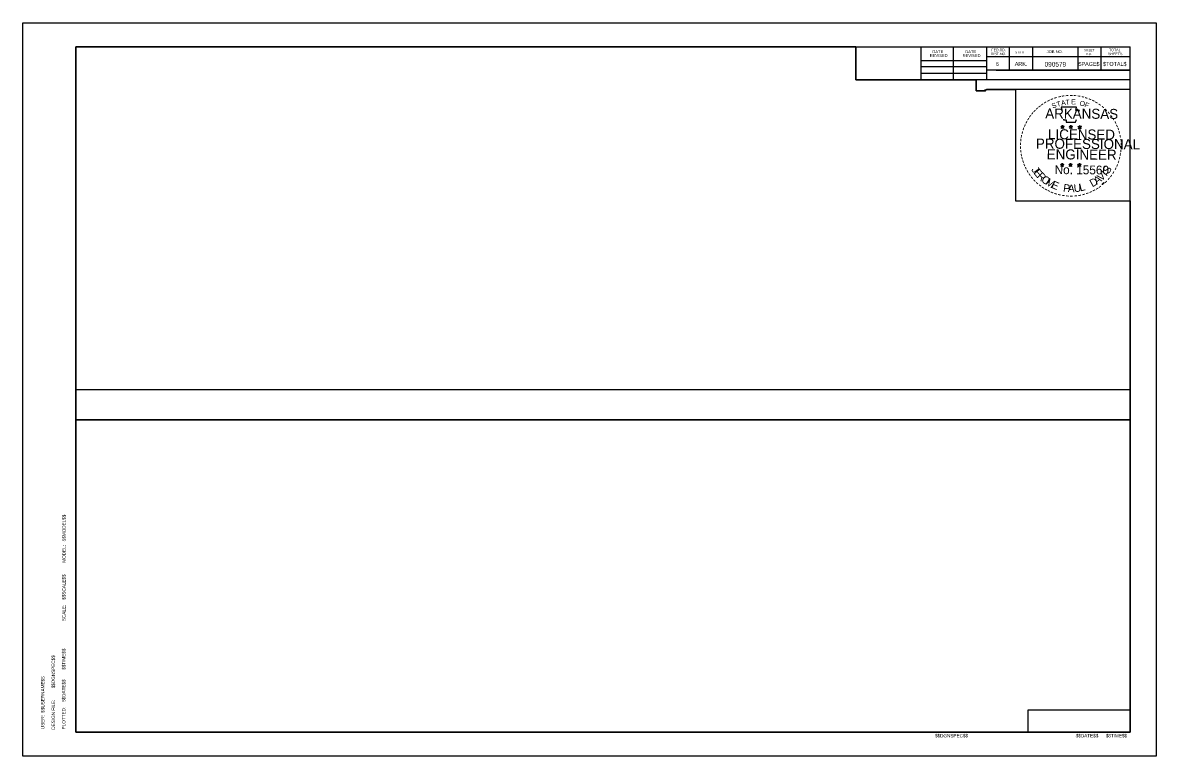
# Model space of a CAD drawing. Extents: x -1.6 to 32.4, y -0.7 to 21.3.
import ezdxf

# ---------------------------------------------------------------- set-up
doc = ezdxf.new("R2010")
doc.units = 0
for name, color, linetype in [('Level 3', 7, 'Continuous'), ('Level 48', 7, 'Continuous'), ('Level 49', 7, 'Continuous'), ('Level 63', 7, 'Continuous'), ('R_Border', 7, 'Continuous'), ('R_Border Notes', 7, 'Continuous'), ('R_Border Prelim', 7, 'Continuous'), ('R_No Plot', 7, 'Continuous')]:
    doc.layers.add(name, color=color, linetype=linetype)

msp = doc.modelspace()

# ---------------------------------------------------------------- linework, layer by layer
at = {"layer": 'Level 3'}
msp.add_lwpolyline([(-0.001, -0.001), (31.617, -0.001), (31.617, 19.265), (27.307, 19.265), (27.211, 19.232), (26.999, 19.232), (26.999, 19.557), (23.391, 19.557), (23.391, 20.545), (23.391, 20.545), (23.391, 20.545), (-0.001, 20.545)], close=True, dxfattribs=at)
at = {"layer": 'Level 48'}
for p, q in [((-0.001, 20.545), (-0.001, -0.001)), ((23.391, 19.557), (23.391, 20.545)), ((26.999, 19.557), (23.391, 19.557)), ((26.999, 19.232), (26.999, 19.557)), ((27.211, 19.232), (26.999, 19.232)), ((27.307, 19.265), (27.211, 19.232)), ((31.617, 19.265), (27.307, 19.265)), ((31.617, -0.001), (31.617, 19.265)), ((-0.001, -0.001), (31.617, -0.001))]:
    msp.add_line(p, q, dxfattribs=at)
msp.add_lwpolyline([(23.391, 20.545), (23.391, 20.545), (23.391, 20.545), (-0.001, 20.545)], dxfattribs=at)
at = {"layer": 'Level 63'}
for p, q in [((-0.002, 0.481), (-0.001, 10.271)), ((-0.001, 10.271), (31.617, 10.271)), ((31.617, 10.271), (31.617, -0.001)), ((-0.001, -0.001), (-0.002, 0.481)), ((-0.002, 0.481), (-0.002, 0.481)), ((31.617, -0.001), (-0.001, -0.001))]:
    msp.add_line(p, q, dxfattribs=at)
for points in [[(-0.001, 20.545), (23.391, 20.545), (23.391, 19.557), (27, 19.557), (27, 19.233), (27.274, 19.233), (27.307, 19.265), (28.175, 19.265), (28.175, 15.933), (31.617, 15.933), (31.617, 9.363), (-0.001, 9.363)], [(-0.001, 9.363), (31.617, 9.363), (31.617, 0.657), (28.548, 0.657), (28.546, 0), (-0.001, -0.001)]]:
    msp.add_lwpolyline(points, close=True, dxfattribs=at)
at = {"layer": 'R_Border'}
msp.add_lwpolyline([(-1.598, 21.273), (32.402, 21.273), (32.402, -0.727), (-1.598, -0.727)], close=True, dxfattribs=at)
at = {"layer": 'R_Border Prelim'}
for p, q in [((29.534, 18.159), (29.588, 18.142)), ((29.534, 18.159), (29.573, 18.157)), ((29.534, 18.159), (29.573, 18.155)), ((29.534, 18.159), (29.569, 18.149)), ((29.534, 18.159), (29.569, 18.144)), ((29.534, 18.159), (29.569, 18.142)), ((29.534, 18.159), (29.569, 18.136)), ((29.556, 18.097), (29.588, 18.142)), ((29.556, 18.097), (29.569, 18.14)), ((29.556, 18.097), (29.573, 18.135)), ((29.556, 18.097), (29.575, 18.133)), ((29.556, 18.097), (29.581, 18.129)), ((29.556, 18.097), (29.588, 18.129)), ((29.556, 18.097), (29.588, 18.125)), ((29.588, 18.199), (29.581, 18.159)), ((29.588, 18.199), (29.581, 18.162)), ((29.588, 18.199), (29.584, 18.162)), ((29.588, 18.142), (29.588, 18.199)), ((29.588, 18.199), (29.597, 18.159)), ((29.588, 18.199), (29.595, 18.162)), ((29.588, 18.199), (29.59, 18.162)), ((29.64, 18.159), (29.588, 18.142)), ((29.619, 18.096), (29.588, 18.142)), ((29.619, 18.096), (29.588, 18.129)), ((29.619, 18.096), (29.588, 18.125)), ((29.64, 18.159), (29.592, 18.155)), ((29.619, 18.096), (29.592, 18.129)), ((29.64, 18.159), (29.597, 18.151)), ((29.64, 18.159), (29.597, 18.148)), ((29.619, 18.096), (29.597, 18.14)), ((29.619, 18.096), (29.597, 18.135)), ((29.619, 18.096), (29.603, 18.142)), ((29.64, 18.159), (29.605, 18.148)), ((29.64, 18.159), (29.61, 18.144)), ((29.64, 18.159), (29.612, 18.142)), ((29.784, 18.157), (29.838, 18.142)), ((29.784, 18.157), (29.823, 18.155)), ((29.784, 18.157), (29.823, 18.151)), ((29.784, 18.157), (29.823, 18.149)), ((29.784, 18.157), (29.821, 18.142)), ((29.784, 18.157), (29.821, 18.14)), ((29.784, 18.157), (29.821, 18.135)), ((29.807, 18.096), (29.838, 18.142)), ((29.807, 18.096), (29.823, 18.136)), ((29.807, 18.096), (29.823, 18.135)), ((29.807, 18.096), (29.825, 18.133)), ((29.807, 18.096), (29.831, 18.127)), ((29.807, 18.096), (29.838, 18.127)), ((29.807, 18.096), (29.838, 18.125)), ((29.838, 18.196), (29.831, 18.157)), ((29.838, 18.196), (29.831, 18.159)), ((29.838, 18.196), (29.832, 18.159)), ((29.838, 18.142), (29.838, 18.196)), ((29.838, 18.196), (29.847, 18.157)), ((29.838, 18.196), (29.845, 18.159)), ((29.838, 18.196), (29.84, 18.159)), ((29.89, 18.157), (29.838, 18.142)), ((29.869, 18.096), (29.838, 18.142)), ((29.869, 18.096), (29.838, 18.127)), ((29.869, 18.096), (29.838, 18.125)), ((29.89, 18.157), (29.844, 18.155)), ((29.869, 18.096), (29.844, 18.127)), ((29.89, 18.157), (29.847, 18.149)), ((29.89, 18.157), (29.847, 18.148)), ((29.869, 18.096), (29.847, 18.14)), ((29.869, 18.096), (29.847, 18.133)), ((29.869, 18.096), (29.853, 18.14)), ((29.89, 18.157), (29.855, 18.144)), ((29.89, 18.157), (29.86, 18.142)), ((29.89, 18.157), (29.862, 18.14)), ((30.049, 18.155), (30.103, 18.136)), ((30.049, 18.155), (30.092, 18.149)), ((30.049, 18.155), (30.088, 18.148)), ((30.049, 18.155), (30.088, 18.144)), ((30.049, 18.155), (30.086, 18.14)), ((30.049, 18.155), (30.086, 18.135)), ((30.049, 18.155), (30.086, 18.135)), ((30.07, 18.094), (30.103, 18.136)), ((30.07, 18.094), (30.088, 18.135)), ((30.07, 18.094), (30.092, 18.129)), ((30.07, 18.094), (30.092, 18.127)), ((30.07, 18.094), (30.103, 18.127)), ((30.07, 18.094), (30.099, 18.125)), ((30.07, 18.094), (30.107, 18.12)), ((30.103, 18.192), (30.094, 18.157)), ((30.103, 18.192), (30.099, 18.155)), ((30.103, 18.192), (30.099, 18.155)), ((30.103, 18.136), (30.103, 18.192)), ((30.103, 18.192), (30.114, 18.155)), ((30.103, 18.192), (30.11, 18.155)), ((30.103, 18.192), (30.107, 18.155)), ((30.155, 18.155), (30.103, 18.136)), ((30.133, 18.094), (30.103, 18.136)), ((30.133, 18.094), (30.103, 18.127)), ((30.133, 18.094), (30.103, 18.12)), ((30.155, 18.155), (30.108, 18.149)), ((30.133, 18.094), (30.108, 18.125)), ((30.155, 18.155), (30.114, 18.148)), ((30.155, 18.155), (30.114, 18.142)), ((30.133, 18.094), (30.114, 18.135)), ((30.133, 18.094), (30.114, 18.129)), ((30.133, 18.094), (30.118, 18.135)), ((30.155, 18.155), (30.121, 18.14)), ((30.155, 18.155), (30.123, 18.14)), ((30.155, 18.155), (30.129, 18.136)), ((29.527, 17.021), (29.581, 17.005)), ((29.527, 17.021), (29.566, 17.019)), ((29.527, 17.021), (29.564, 17.014)), ((29.527, 17.021), (29.564, 17.014)), ((29.527, 17.021), (29.564, 17.006)), ((29.527, 17.021), (29.564, 17.005)), ((29.527, 17.021), (29.564, 17.003)), ((29.545, 16.964), (29.581, 17.005)), ((29.545, 16.964), (29.564, 17.005)), ((29.581, 17.062), (29.569, 17.025)), ((29.581, 17.062), (29.573, 17.021)), ((29.581, 17.062), (29.575, 17.021)), ((29.581, 17.005), (29.581, 17.062)), ((29.581, 17.062), (29.588, 17.021)), ((29.581, 17.062), (29.588, 17.021)), ((29.581, 17.062), (29.581, 17.021)), ((29.632, 17.021), (29.581, 17.005)), ((29.61, 16.96), (29.581, 17.005)), ((29.632, 17.021), (29.584, 17.019)), ((29.632, 17.021), (29.588, 17.014)), ((29.632, 17.021), (29.588, 17.012)), ((29.61, 16.96), (29.588, 17.005)), ((29.632, 17.021), (29.595, 17.01)), ((29.61, 16.96), (29.595, 17.005)), ((29.632, 17.021), (29.599, 17.006)), ((29.632, 17.021), (29.603, 17.005)), ((29.777, 17.021), (29.831, 17.005)), ((29.777, 17.021), (29.816, 17.018)), ((29.777, 17.021), (29.816, 17.014)), ((29.777, 17.021), (29.816, 17.012)), ((29.777, 17.021), (29.814, 17.006)), ((29.777, 17.021), (29.814, 17.003)), ((29.777, 17.021), (29.814, 16.999)), ((29.795, 16.96), (29.831, 17.005)), ((29.795, 16.96), (29.816, 17.003)), ((29.831, 17.058), (29.821, 17.021)), ((29.831, 17.058), (29.823, 17.021)), ((29.831, 17.058), (29.825, 17.021)), ((29.831, 17.005), (29.831, 17.058)), ((29.831, 17.058), (29.838, 17.019)), ((29.831, 17.058), (29.838, 17.019)), ((29.831, 17.058), (29.831, 17.021)), ((29.881, 17.019), (29.831, 17.005)), ((29.86, 16.96), (29.831, 17.005)), ((29.881, 17.019), (29.836, 17.019)), ((29.881, 17.019), (29.838, 17.012)), ((29.881, 17.019), (29.838, 17.012)), ((29.86, 16.96), (29.838, 17.003)), ((29.881, 17.019), (29.845, 17.006)), ((29.86, 16.96), (29.845, 17.003)), ((29.881, 17.019), (29.851, 17.005)), ((29.881, 17.019), (29.853, 17.003)), ((30.042, 17.018), (30.095, 16.999)), ((30.042, 17.018), (30.081, 17.014)), ((30.042, 17.018), (30.081, 17.01)), ((30.042, 17.018), (30.079, 17.006)), ((30.042, 17.018), (30.079, 17.003)), ((30.042, 17.018), (30.077, 16.999)), ((30.042, 17.018), (30.077, 16.995)), ((30.095, 17.056), (30.086, 17.018)), ((30.095, 17.056), (30.088, 17.018)), ((30.095, 17.056), (30.092, 17.018)), ((30.095, 16.999), (30.095, 17.056)), ((30.095, 17.056), (30.103, 17.018)), ((30.095, 17.056), (30.103, 17.018)), ((30.095, 17.056), (30.095, 17.018)), ((30.147, 17.018), (30.095, 16.999)), ((30.147, 17.018), (30.101, 17.014)), ((30.147, 17.018), (30.103, 17.01)), ((30.147, 17.018), (30.103, 17.006)), ((30.147, 17.018), (30.114, 17.005)), ((30.147, 17.018), (30.116, 16.999)), ((30.147, 17.018), (30.118, 16.999)), ((29.545, 16.964), (29.566, 16.997)), ((29.545, 16.964), (29.568, 16.997)), ((29.545, 16.964), (29.581, 16.995)), ((29.545, 16.964), (29.573, 16.992)), ((29.545, 16.964), (29.581, 16.99)), ((29.61, 16.96), (29.577, 16.99)), ((29.61, 16.96), (29.581, 16.992)), ((29.61, 16.96), (29.582, 16.992)), ((29.61, 16.96), (29.588, 16.997)), ((29.795, 16.96), (29.816, 16.995)), ((29.795, 16.96), (29.818, 16.995)), ((29.795, 16.96), (29.823, 16.992)), ((29.795, 16.96), (29.831, 16.992)), ((29.795, 16.96), (29.831, 16.988)), ((29.86, 16.96), (29.829, 16.988)), ((29.86, 16.96), (29.831, 16.992)), ((29.86, 16.96), (29.832, 16.992)), ((29.86, 16.96), (29.838, 16.997)), ((30.062, 16.956), (30.095, 16.999)), ((30.062, 16.956), (30.079, 16.999)), ((30.062, 16.956), (30.081, 16.992)), ((30.062, 16.956), (30.084, 16.992)), ((30.062, 16.956), (30.088, 16.988)), ((30.062, 16.956), (30.094, 16.988)), ((30.062, 16.956), (30.095, 16.984)), ((30.125, 16.956), (30.094, 16.988)), ((30.125, 16.956), (30.094, 16.984)), ((30.125, 16.956), (30.095, 16.999)), ((30.125, 16.956), (30.099, 16.988)), ((30.125, 16.956), (30.103, 16.992)), ((30.125, 16.956), (30.107, 16.999)), ((30.125, 16.956), (30.108, 16.999))]:
    msp.add_line(p, q, dxfattribs=at)
for points in [[(29.545, 18.742), (29.582, 18.616)], [(30.071, 18.6), (30.094, 18.644), (29.988, 18.638), (30.012, 18.738), (29.545, 18.742)], [(29.618, 18.377), (29.618, 18.362), (29.701, 18.361), (29.694, 18.292), (29.973, 18.29), (30.003, 18.368)], [(29.588, 18.199), (29.619, 18.096), (29.534, 18.159), (29.64, 18.159), (29.556, 18.097), (29.588, 18.199)], [(29.838, 18.196), (29.869, 18.096), (29.784, 18.157), (29.89, 18.157), (29.807, 18.096), (29.838, 18.196)], [(30.103, 18.192), (30.133, 18.094), (30.049, 18.155), (30.155, 18.155), (30.07, 18.094), (30.103, 18.192)], [(29.581, 17.062), (29.61, 16.96), (29.527, 17.021), (29.632, 17.021), (29.545, 16.964), (29.581, 17.062)], [(29.831, 17.058), (29.86, 16.96), (29.777, 17.021), (29.881, 17.019), (29.795, 16.96), (29.831, 17.058)], [(30.095, 17.056), (30.125, 16.956), (30.042, 17.018), (30.147, 17.018), (30.062, 16.956), (30.095, 17.056)], [(30.79, 16.415), (30.783, 16.44), (30.827, 16.477)], [(30.824, 16.482), (30.831, 16.46), (30.786, 16.421)], [(30.831, 16.464), (30.786, 16.425)], [(30.831, 16.46), (30.788, 16.423)]]:
    msp.add_lwpolyline(points, dxfattribs=at)
for centre, radius in [((29.589, 18.141), 0.0259), ((29.589, 18.141), 0.0234), ((29.589, 18.141), 0.0217), ((29.589, 18.141), 0.0199), ((29.589, 18.141), 0.0174), ((29.589, 18.141), 0.0161), ((29.589, 18.141), 0.0149), ((29.589, 18.141), 0.0128), ((29.589, 18.141), 0.0112), ((29.589, 18.141), 0.00933), ((29.589, 18.141), 0.00744), ((29.589, 18.141), 0.00555), ((29.589, 18.141), 0.00445), ((29.589, 18.141), 0.00216), ((29.839, 18.139), 0.0259), ((29.839, 18.139), 0.0234), ((29.839, 18.139), 0.0217), ((29.839, 18.139), 0.0199), ((29.839, 18.139), 0.0174), ((29.839, 18.139), 0.0161), ((29.839, 18.139), 0.0149), ((29.839, 18.139), 0.0128), ((29.839, 18.139), 0.0112), ((29.839, 18.139), 0.00933), ((29.839, 18.139), 0.00744), ((29.839, 18.139), 0.00555), ((29.839, 18.139), 0.00445), ((29.839, 18.139), 0.00216), ((30.105, 18.136), 0.0259), ((30.105, 18.136), 0.0234), ((30.105, 18.136), 0.0217), ((30.105, 18.136), 0.0199), ((30.105, 18.136), 0.0174), ((30.105, 18.136), 0.0161), ((30.105, 18.136), 0.0149), ((30.105, 18.136), 0.0128), ((30.105, 18.136), 0.0112), ((30.105, 18.136), 0.00933), ((30.105, 18.136), 0.00744), ((30.105, 18.136), 0.00555), ((30.105, 18.136), 0.00445), ((30.105, 18.136), 0.00216), ((29.58, 17.004), 0.0259), ((29.58, 17.004), 0.0234), ((29.58, 17.004), 0.0217), ((29.58, 17.004), 0.0199), ((29.58, 17.004), 0.0174), ((29.58, 17.004), 0.0161), ((29.58, 17.004), 0.0149), ((29.58, 17.004), 0.0128), ((29.58, 17.004), 0.0112), ((29.58, 17.004), 0.00933), ((29.58, 17.004), 0.00744), ((29.58, 17.004), 0.00555), ((29.58, 17.004), 0.00445), ((29.58, 17.004), 0.00216), ((29.831, 17.003), 0.0259), ((29.831, 17.003), 0.0234), ((29.831, 17.003), 0.0217), ((29.831, 17.003), 0.0199), ((29.831, 17.003), 0.0174), ((29.831, 17.003), 0.0161), ((29.831, 17.003), 0.0149), ((29.831, 17.003), 0.0128), ((29.831, 17.003), 0.0112), ((29.831, 17.003), 0.00933), ((29.831, 17.003), 0.00744), ((29.831, 17.003), 0.00555), ((29.831, 17.003), 0.00445), ((29.831, 17.003), 0.00216), ((30.096, 16.999), 0.0259), ((30.096, 16.999), 0.0234), ((30.096, 16.999), 0.0217), ((30.096, 16.999), 0.0199), ((30.096, 16.999), 0.0174), ((30.096, 16.999), 0.0161), ((30.096, 16.999), 0.0149), ((30.096, 16.999), 0.0128), ((30.096, 16.999), 0.0112), ((30.096, 16.999), 0.00933), ((30.096, 16.999), 0.00744), ((30.096, 16.999), 0.00555), ((30.096, 16.999), 0.00445), ((30.096, 16.999), 0.00216)]:
    msp.add_circle(centre, radius, dxfattribs=at)
at = {"layer": 'R_No Plot'}
for p, q in [((-0.001, 20.545), (31.617, 20.545)), ((-0.001, -0.001), (-0.001, 20.545)), ((25.353, 19.557), (25.353, 20.545)), ((26.321, 19.557), (26.321, 20.545)), ((27.307, 20.545), (27.307, 19.557)), ((27.991, 20.545), (27.991, 19.851)), ((28.685, 20.545), (28.685, 19.851)), ((30.043, 20.545), (30.043, 19.851)), ((30.737, 20.545), (30.737, 19.851)), ((31.617, -0.001), (31.617, 20.545)), ((25.353, 20.143), (27.307, 20.143)), ((31.617, 20.251), (27.307, 20.251)), ((31.617, 20.253), (31.617, 20.253)), ((25.353, 19.957), (27.307, 19.957)), ((25.353, 19.763), (27.307, 19.763)), ((31.617, 19.851), (27.307, 19.851)), ((27.603, 19.851), (31.617, 19.851)), ((31.617, 19.557), (25.353, 19.557)), ((31.617, -0.001), (-0.001, -0.001))]:
    msp.add_line(p, q, dxfattribs=at)

# ---------------------------------------------------------------- texts
at = {"layer": 'Level 49'}
msp.add_text('JOB NO.', height=0.0879, dxfattribs=at).set_placement((29.112, 20.36))
at = {"layer": 'R_Border Notes'}
for s, p in [('$$DGNSPEC$$', (25.764, -0.159)), ('$$DATE$$', (29.986, -0.159)), ('$$TIME$$', (30.887, -0.159))]:
    msp.add_text(s, height=0.1, dxfattribs=at).set_placement(p)
at = {"layer": 'R_Border Prelim'}
for s, height, rotation, p in [('-', 0.24, 18.7785, (29.356, 18.914)), ('-', 0.24, 13.2326, (29.469, 18.95)), ('-', 0.24, 9.8217, (29.569, 18.974)), ('-', 0.24, 5.4992, (29.681, 18.989)), ('-', 0.24, 359.7886, (29.795, 19)), ('-', 0.24, 357.3454, (29.907, 18.996)), ('-', 0.24, 351.7641, (30.016, 18.987)), ('-', 0.24, 346.8073, (30.125, 18.97)), ('-', 0.24, 341.9386, (30.22, 18.944)), ('-', 0.24, 42.5646, (28.851, 18.596)), ('-', 0.24, 38.5531, (28.917, 18.657)), ('-', 0.24, 35.8341, (28.988, 18.714)), ('-', 0.24, 33.666, (29.075, 18.774)), ('ARKANSAS', 0.3002, 359.6024, (29.069, 18.401)), ('-', 0.24, 28.3942, (29.166, 18.827)), ('-', 0.24, 23.9096, (29.26, 18.874)), ('S', 0.15, 21.1964, (29.295, 18.696)), ('T', 0.15, 16.006, (29.432, 18.746)), ('A', 0.15, 10.8156, (29.558, 18.783)), ('T', 0.15, 5.6252, (29.686, 18.807)), ('E', 0.15, 0.4347, (29.851, 18.822)), ('O', 0.15, 350.0539, (30.092, 18.79)), ('F', 0.15, 339.6731, (30.234, 18.753)), ('-', 0.24, 337.4575, (30.329, 18.911)), ('-', 0.24, 333.7235, (30.425, 18.872)), ('-', 0.24, 329.2433, (30.51, 18.827)), ('-', 0.24, 325.4651, (30.607, 18.77)), ('-', 0.24, 320.1321, (30.698, 18.707)), ('-', 0.24, 57.673, (28.61, 18.286)), ('-', 0.24, 53.8349, (28.658, 18.368)), ('-', 0.24, 50.2166, (28.721, 18.453)), ('-', 0.24, 48.0255, (28.782, 18.525)), ('-', 0.24, 315.181, (30.788, 18.633)), ('-', 0.24, 309.4821, (30.872, 18.549)), ('-', 0.24, 306.2546, (30.948, 18.459)), ('-', 0.21, 303.2777, (31.022, 18.372)), ('-', 0.24, 71.9969, (28.489, 18.01)), ('-', 0.24, 67.3767, (28.525, 18.105)), ('-', 0.24, 62.4738, (28.564, 18.196)), ('LICENSED', 0.3002, 359.6024, (29.153, 17.779)), ('-', 0.24, 299.2708, (31.068, 18.281)), ('-', 0.24, 294.2652, (31.116, 18.188)), ('-', 0.24, 290.1752, (31.157, 18.105)), ('-', 0.24, 284.7257, (31.188, 18.016)), ('-', 0.24, 88.6646, (28.423, 17.588)), ('-', 0.24, 84.7887, (28.426, 17.694)), ('-', 0.24, 80.8037, (28.438, 17.797)), ('-', 0.24, 75.0634, (28.46, 17.903)), ('PROFESSIONAL', 0.30016, 359.6024, (28.79, 17.497)), ('-', 0.24, 280.1517, (31.218, 17.903)), ('-', 0.24, 276.1986, (31.244, 17.788)), ('-', 0.24, 93.7983, (28.426, 17.479)), ('-', 0.24, 98.5503, (28.438, 17.377)), ('-', 0.24, 101.3173, (28.454, 17.268)), ('ENGINEER', 0.3002, 359.6024, (29.114, 17.177)), ('-', 0.24, 260.5977, (31.238, 17.388)), ('-', 0.24, 263.1196, (31.251, 17.486)), ('-', 0.24, 273.9325, (31.251, 17.679)), ('-', 0.24, 269.5431, (31.255, 17.586)), ('-', 0.24, 105.0602, (28.48, 17.179)), ('-', 0.24, 108.6898, (28.512, 17.086)), ('-', 0.24, 113.6667, (28.549, 16.993)), ('-', 0.24, 247.4911, (31.163, 17.075)), ('-', 0.24, 252.4705, (31.196, 17.177)), ('-', 0.24, 255.365, (31.222, 17.286)), ('-', 0.24, 115.3313, (28.595, 16.901)), ('-', 0.24, 120.0495, (28.647, 16.812)), ('-', 0.24, 125.4958, (28.708, 16.729)), ('-', 0.24, 130.3205, (28.775, 16.645)), ('J', 0.231, 303.9209, (28.641, 16.865)), ('E', 0.231, 308.618, (28.706, 16.769)), ('R', 0.231, 314.7784, (28.803, 16.65)), ('O', 0.231, 321.6761, (28.926, 16.531)), ('No. 15560', 0.2641, 359.6024, (29.351, 16.733)), ('A', 0.231, 34.8903, (30.618, 16.411)), ('V', 0.231, 41.4844, (30.75, 16.507)), ('I', 0.231, 49.9999, (30.904, 16.652)), ('S', 0.231, 53.5227, (30.961, 16.718)), ('-', 0.24, 233.4476, (31.003, 16.773)), ('-', 0.24, 238.6736, (31.061, 16.871)), ('-', 0.24, 244.2221, (31.12, 16.982)), ('-', 0.24, 133.8262, (28.852, 16.564)), ('-', 0.24, 138.5362, (28.928, 16.493)), ('-', 0.24, 144.2487, (29.016, 16.432)), ('-', 0.24, 147.6922, (29.097, 16.375)), ('M', 0.231, 328.1357, (29.053, 16.434)), ('E', 0.231, 336.4966, (29.232, 16.33)), ('P', 0.231, 351.9783, (29.596, 16.211)), ('A', 0.231, 357.9896, (29.744, 16.192)), ('U', 0.231, 5.7635, (29.937, 16.19)), ('L', 0.231, 13.0992, (30.118, 16.213)), ('D', 0.231, 28.5809, (30.481, 16.334)), ('-', 0.24, 211.8515, (30.62, 16.401)), ('-', 0.24, 215.3387, (30.699, 16.458)), ('-', 0.24, 225.3677, (30.862, 16.604)), ('-', 0.24, 233.4476, (30.933, 16.691)), ('-', 0.24, 151.1728, (29.182, 16.327)), ('-', 0.24, 154.2026, (29.264, 16.288)), ('-', 0.24, 158.1636, (29.356, 16.247)), ('-', 0.24, 162.4007, (29.46, 16.215)), ('-', 0.24, 167.1579, (29.566, 16.191)), ('-', 0.24, 172.7179, (29.681, 16.175)), ('-', 0.24, 176.1207, (29.794, 16.164)), ('-', 0.24, 181.1942, (29.905, 16.167)), ('-', 0.24, 185.4191, (30.027, 16.176)), ('-', 0.24, 190.8882, (30.138, 16.195)), ('-', 0.24, 195.0767, (30.247, 16.225)), ('-', 0.24, 200.3208, (30.349, 16.262)), ('-', 0.24, 203.854, (30.442, 16.302)), ('-', 0.24, 206.9592, (30.536, 16.349))]:
    msp.add_text(s, height=height, rotation=rotation, dxfattribs=at).set_placement(p)
at = {"layer": 'R_No Plot'}
for s, height, p in [('DATE', 0.0879, (25.687, 20.359)), ('DATE', 0.0879, (26.673, 20.359)), ('FED.RD.', 0.0782, (27.455, 20.417)), ('STATE', 0.0684, (28.167, 20.349)), ('JOB NO.', 0.0879, (29.112, 20.36)), ('SHEET', 0.0684, (30.229, 20.417)), ('TOTAL', 0.0782, (30.981, 20.417)), ('REVISED', 0.0879, (25.609, 20.241)), ('REVISED', 0.0879, (26.595, 20.241)), ('DIST.NO.', 0.0782, (27.435, 20.299)), ('6', 0.117, (27.591, 19.977)), ('ARK.', 0.1172, (28.157, 19.977)), ('090579', 0.14, (29.051, 19.956)), ('$PAGE$', 0.1172, (30.067, 19.977)), ('NO.', 0.0684, (30.307, 20.299)), ('$TOTAL$', 0.1172, (30.806, 19.977)), ('SHEETS', 0.0782, (30.953, 20.299))]:
    msp.add_text(s, height=height, dxfattribs=at).set_placement(p)
for s, p in [('$$MODEL$$', (-0.31, 5.721)), ('MODEL:', (-0.31, 5.08)), ('$$SCALE$$', (-0.313, 3.969)), ('SCALE:', (-0.313, 3.328)), ('$$TIME$$', (-0.316, 1.867)), ('$$DGNSPEC$$', (-0.632, 1.314)), ('$$USERNAME$$', (-0.944, 0.58)), ('$$DATE$$', (-0.316, 0.903)), ('DESIGN FILE:', (-0.632, 0.073)), ('PLOTTED:', (-0.316, 0.081)), ('USER:', (-0.948, 0.089))]:
    msp.add_text(s, height=0.1, rotation=90, dxfattribs=at).set_placement(p)

doc.saveas('drawing.dxf')
